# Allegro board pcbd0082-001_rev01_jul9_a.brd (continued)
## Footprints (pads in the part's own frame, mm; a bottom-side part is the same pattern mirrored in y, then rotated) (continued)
C_0402
  rect 0.508x0.533 smd: 1(0,0.419) 2(0,-0.419)
C_0402#2
  custom 0.127x0.127 smd: 1(0,0.5) 2(0,-0.5)
C_0603
  rect 0.864x0.965 smd: 1(0,0.8) 2(0,-0.8)
C_0805
  rect 1.422x1.397 smd: 1(0,1.143) 2(0,-1.143)
C_1206
  rect 1.524x1.524 smd: 1(0,1.676) 2(0,-1.676)
C_1210
  rect 1.372x2.743 smd: 1(-1.422,0) 2(1.422,0)
CON_SAM_SEAM-20-03P5-S-08-2-A-K
  round 1.778 hole 1.27 unplated: (-14.491,-3.048) (14.491,0)
  round 0.635 smd: 1(12.065,4.445) 2(12.065,3.175) 3(12.065,1.905) 4(12.065,0.635) 5(12.065,-0.635) 6(12.065,-1.905) 7(12.065,-3.175) 8(12.065,-4.445) 9(10.795,4.445) 10(10.795,3.175) 11(10.795,1.905) 12(10.795,0.635) 13(10.795,-0.635) 14(10.795,-1.905) 15(10.795,-3.175) 16(10.795,-4.445) 17(9.525,4.445) 18(9.525,3.175) 19(9.525,1.905) 20(9.525,0.635) 21(9.525,-0.635) 22(9.525,-1.905) 23(9.525,-3.175) 24(9.525,-4.445) 25(8.255,4.445) 26(8.255,3.175) 27(8.255,1.905) 28(8.255,0.635) 29(8.255,-0.635) 30(8.255,-1.905) 31(8.255,-3.175) 32(8.255,-4.445) 33(6.985,4.445) 34(6.985,3.175) 35(6.985,1.905) 36(6.985,0.635) 37(6.985,-0.635) 38(6.985,-1.905) 39(6.985,-3.175) 40(6.985,-4.445) 41(5.715,4.445) 42(5.715,3.175) 43(5.715,1.905) 44(5.715,0.635) 45(5.715,-0.635) 46(5.715,-1.905) 47(5.715,-3.175) 48(5.715,-4.445) 49(4.445,4.445) 50(4.445,3.175) 51(4.445,1.905) 52(4.445,0.635) 53(4.445,-0.635) 54(4.445,-1.905) 55(4.445,-3.175) 56(4.445,-4.445) 57(3.175,4.445) 58(3.175,3.175) 59(3.175,1.905) 60(3.175,0.635) 61(3.175,-0.635) 62(3.175,-1.905) 63(3.175,-3.175) 64(3.175,-4.445) 65(1.905,4.445) 66(1.905,3.175) 67(1.905,1.905) 68(1.905,0.635) 69(1.905,-0.635) 70(1.905,-1.905) 71(1.905,-3.175) 72(1.905,-4.445) 73(0.635,4.445) 74(0.635,3.175) 75(0.635,1.905) 76(0.635,0.635) 77(0.635,-0.635) 78(0.635,-1.905) 79(0.635,-3.175) 80(0.635,-4.445) 81(-0.635,4.445) 82(-0.635,3.175) 83(-0.635,1.905) 84(-0.635,0.635) 85(-0.635,-0.635) 86(-0.635,-1.905) 87(-0.635,-3.175) 88(-0.635,-4.445) 89(-1.905,4.445) 90(-1.905,3.175) 91(-1.905,1.905) 92(-1.905,0.635) 93(-1.905,-0.635) 94(-1.905,-1.905) 95(-1.905,-3.175) 96(-1.905,-4.445) 97(-3.175,4.445) 98(-3.175,3.175) 99(-3.175,1.905) 100(-3.175,0.635) 101(-3.175,-0.635) 102(-3.175,-1.905) 103(-3.175,-3.175) 104(-3.175,-4.445) 105(-4.445,4.445) 106(-4.445,3.175) 107(-4.445,1.905) 108(-4.445,0.635) 109(-4.445,-0.635) 110(-4.445,-1.905) 111(-4.445,-3.175) 112(-4.445,-4.445) 113(-5.715,4.445) 114(-5.715,3.175) 115(-5.715,1.905) 116(-5.715,0.635) 117(-5.715,-0.635) 118(-5.715,-1.905) 119(-5.715,-3.175) 120(-5.715,-4.445) 121(-6.985,4.445) 122(-6.985,3.175) 123(-6.985,1.905) 124(-6.985,0.635) 125(-6.985,-0.635) 126(-6.985,-1.905) 127(-6.985,-3.175) 128(-6.985,-4.445) 129(-8.255,4.445) 130(-8.255,3.175) 131(-8.255,1.905) 132(-8.255,0.635) 133(-8.255,-0.635) 134(-8.255,-1.905) 135(-8.255,-3.175) 136(-8.255,-4.445) 137(-9.525,4.445) 138(-9.525,3.175) 139(-9.525,1.905) 140(-9.525,0.635) 141(-9.525,-0.635) 142(-9.525,-1.905) 143(-9.525,-3.175) 144(-9.525,-4.445) 145(-10.795,4.445) 146(-10.795,3.175) 147(-10.795,1.905) 148(-10.795,0.635) 149(-10.795,-0.635) 150(-10.795,-1.905) 151(-10.795,-3.175) 152(-10.795,-4.445) 153(-12.065,4.445) 154(-12.065,3.175) 155(-12.065,1.905) 156(-12.065,0.635) 157(-12.065,-0.635) 158(-12.065,-1.905) 159(-12.065,-3.175) 160(-12.065,-4.445)
DHVQFN16_138_98_19P7_EP
  custom 0.07x0.07 smd: 1(-1.702,-0.25) 2(-1.25,-1.194) 3(-0.75,-1.194) 4(-0.25,-1.194) 5(0.25,-1.194) 6(0.75,-1.194) 7(1.25,-1.194) 8(1.702,-0.25) 9(1.702,0.25) 10(1.25,1.194) 11(0.75,1.194) 12(0.25,1.194) 13(-0.25,1.194) 14(-0.75,1.194) 15(-1.25,1.194) 16(-1.702,0.25)
  rect 1.981x0.965 smd: 17(0,0)
FBGA96
  round 0.356 smd: A1(-3.2,6) A2(-2.4,6) A3(-1.6,6) A7(1.6,6) A8(2.4,6) A9(3.2,6) B1(-3.2,5.2) B2(-2.4,5.2) B3(-1.6,5.2) B7(1.6,5.2) B8(2.4,5.2) B9(3.2,5.2) C1(-3.2,4.4) C2(-2.4,4.4) C3(-1.6,4.4) C7(1.6,4.4) C8(2.4,4.4) C9(3.2,4.4) D1(-3.2,3.6) D2(-2.4,3.6) D3(-1.6,3.6) D7(1.6,3.6) D8(2.4,3.6) D9(3.2,3.6) E1(-3.2,2.8) E2(-2.4,2.8) E3(-1.6,2.8) E7(1.6,2.8) E8(2.4,2.8) E9(3.2,2.8) F1(-3.2,2) F2(-2.4,2) F3(-1.6,2) F7(1.6,2) F8(2.4,2) F9(3.2,2) G1(-3.2,1.2) G2(-2.4,1.2) G3(-1.6,1.2) G7(1.6,1.2) G8(2.4,1.2) G9(3.2,1.2) H1(-3.2,0.4) H2(-2.4,0.4) H3(-1.6,0.4) H7(1.6,0.4) H8(2.4,0.4) H9(3.2,0.4) J1(-3.2,-0.4) J2(-2.4,-0.4) J3(-1.6,-0.4) J7(1.6,-0.4) J8(2.4,-0.4) J9(3.2,-0.4) K1(-3.2,-1.2) K2(-2.4,-1.2) K3(-1.6,-1.2) K7(1.6,-1.2) K8(2.4,-1.2) K9(3.2,-1.2) L1(-3.2,-2) L2(-2.4,-2) L3(-1.6,-2) L7(1.6,-2) L8(2.4,-2) L9(3.2,-2) M1(-3.2,-2.8) M2(-2.4,-2.8) M3(-1.6,-2.8) M7(1.6,-2.8) M8(2.4,-2.8) M9(3.2,-2.8) N1(-3.2,-3.6) N2(-2.4,-3.6) N3(-1.6,-3.6) N7(1.6,-3.6) N8(2.4,-3.6) N9(3.2,-3.6) P1(-3.2,-4.4) P2(-2.4,-4.4) P3(-1.6,-4.4) P7(1.6,-4.4) P8(2.4,-4.4) P9(3.2,-4.4) R1(-3.2,-5.2) R2(-2.4,-5.2) R3(-1.6,-5.2) R7(1.6,-5.2) R8(2.4,-5.2) R9(3.2,-5.2) T1(-3.2,-6) T2(-2.4,-6) T3(-1.6,-6) T7(1.6,-6) T8(2.4,-6) T9(3.2,-6)
HDR_2X15_1000_240_50_SMT_SHF
  rect 0.737x2.921 smd: 1(-8.89,-1.968) 2(-8.89,1.968) 3(-7.62,-1.968) 4(-7.62,1.968) 5(-6.35,-1.968) 6(-6.35,1.968) 7(-5.08,-1.968) 8(-5.08,1.968) 9(-3.81,-1.968) 10(-3.81,1.968) 11(-2.54,-1.968) 12(-2.54,1.968) 13(-1.27,-1.968) 14(-1.27,1.968) 15(0,-1.968) 16(0,1.968) 17(1.27,-1.968) 18(1.27,1.968) 19(2.54,-1.968) 20(2.54,1.968) 21(3.81,-1.968) 22(3.81,1.968) 23(5.08,-1.968) 24(5.08,1.968) 25(6.35,-1.968) 26(6.35,1.968) 27(7.62,-1.968) 28(7.62,1.968) 29(8.89,-1.968) 30(8.89,1.968)
IND_295_425_SMT_SLC1175
  rect 2.362x3.404 smd: 1(0,4.178) 2(0,-4.178)
IND_SMT_4X4X2P1
  rect 1.372x3.581 smd: 1(-1.219,0) 2(1.219,0)
IND_SMT_2520
  rect 1.194x2.337 smd: 1(-1.13,0) 2(1.13,0)
MG132_8_8_0P5MM
  round 1.067 smd: (-5.207,4.826) (4.826,-5.588)
  round 0.254 smd: A1(-3.25,3.25) A2(-2.75,3.25) A3(-2.25,3.25) A4(-1.75,3.25) A5(-1.25,3.25) A6(-0.75,3.25) A7(-0.25,3.25) A8(0.25,3.25) A9(0.75,3.25) A10(1.25,3.25) A11(1.75,3.25) A12(2.25,3.25) A13(2.75,3.25) A14(3.25,3.25) B1(-3.25,2.75) B2(-2.75,2.75) B5(-1.25,2.75) B9(0.75,2.75) B12(2.25,2.75) B13(2.75,2.75) B14(3.25,2.75) C1(-3.25,2.25) C3(-2.25,2.25) C4(-1.75,2.25) C5(-1.25,2.25) C6(-0.75,2.25) C7(-0.25,2.25) C8(0.25,2.25) C9(0.75,2.25) C10(1.25,2.25) C11(1.75,2.25) C12(2.25,2.25) C14(3.25,2.25) D1(-3.25,1.75) D3(-2.25,1.75) D12(2.25,1.75) D14(3.25,1.75) E1(-3.25,1.25) E3(-2.25,1.25) E12(2.25,1.25) E13(2.75,1.25) E14(3.25,1.25) F1(-3.25,0.75) F3(-2.25,0.75) F12(2.25,0.75) F14(3.25,0.75) G1(-3.25,0.25) G3(-2.25,0.25) G12(2.25,0.25) G14(3.25,0.25) H1(-3.25,-0.25) H3(-2.25,-0.25) H12(2.25,-0.25) H14(3.25,-0.25) J1(-3.25,-0.75) J3(-2.25,-0.75) J12(2.25,-0.75) J14(3.25,-0.75) K1(-3.25,-1.25) K3(-2.25,-1.25) K12(2.25,-1.25) K14(3.25,-1.25) L1(-3.25,-1.75) L3(-2.25,-1.75) L12(2.25,-1.75) L14(3.25,-1.75) M1(-3.25,-2.25) M3(-2.25,-2.25) M4(-1.75,-2.25) M5(-1.25,-2.25) M6(-0.75,-2.25) M7(-0.25,-2.25) M8(0.25,-2.25) M9(0.75,-2.25) M10(1.25,-2.25) M11(1.75,-2.25) M12(2.25,-2.25) M14(3.25,-2.25) N1(-3.25,-2.75) N2(-2.75,-2.75) N5(-1.25,-2.75) N7(-0.25,-2.75) N9(0.75,-2.75) N14(3.25,-2.75) P1(-3.25,-3.25) P2(-2.75,-3.25) P3(-2.25,-3.25) P4(-1.75,-3.25) P5(-1.25,-3.25) P6(-0.75,-3.25) P7(-0.25,-3.25) P8(0.25,-3.25) P9(0.75,-3.25) P10(1.25,-3.25) P11(1.75,-3.25) P12(2.25,-3.25) P13(2.75,-3.25) P14(3.25,-3.25)
  round 0.305 hole 0.127: B3(-2.25,2.75) B4(-1.75,2.75) B6(-0.75,2.75) B7(-0.25,2.75) B8(0.25,2.75) B10(1.25,2.75) B11(1.75,2.75) C2(-2.75,2.25) C13(2.75,2.25) D2(-2.75,1.75) D13(2.75,1.75) E2(-2.75,1.25) F2(-2.75,0.75) F13(2.75,0.75) G2(-2.75,0.25) G13(2.75,0.25) H2(-2.75,-0.25) H13(2.75,-0.25) J2(-2.75,-0.75) J13(2.75,-0.75) K2(-2.75,-1.25) K13(2.75,-1.25) L2(-2.75,-1.75) L13(2.75,-1.75) M2(-2.75,-2.25) M13(2.75,-2.25) N3(-2.25,-2.75) N4(-1.75,-2.75) N6(-0.75,-2.75) N8(0.25,-2.75) N10(1.25,-2.75) N11(1.75,-2.75) N12(2.25,-2.75) N13(2.75,-2.75)
MSOP8_193_25P6
  rect 1.524x0.406 smd: 1(-2.159,0.975) 2(-2.159,0.325) 3(-2.159,-0.325) 4(-2.159,-0.975) 5(2.159,-0.975) 6(2.159,-0.325) 7(2.159,0.325) 8(2.159,0.975)
QFN16_0300X0300X0090_0050_EP-MCRL
  rect 0.483x0.28 smd: 1(-1.36,0.75) 2(-1.36,0.25) 3(-1.36,-0.25) 4(-1.36,-0.75) 9(1.36,-0.75) 10(1.36,-0.25) 11(1.36,0.25) 12(1.36,0.75)
  rect 0.28x0.483 smd: 5(-0.75,-1.36) 6(-0.25,-1.36) 7(0.25,-1.36) 8(0.75,-1.36) 13(0.75,1.36) 14(0.25,1.36) 15(-0.25,1.36) 16(-0.75,1.36)
  rect 1.7x1.7 smd: 17(0,0)
QFN20_197_126_19P7_EP
  rect 0.66x0.279 smd: 1(-2.527,0.75) 2(-2.527,0.25) 3(-2.527,-0.25) 4(-2.527,-0.75) 11(2.527,-0.75) 12(2.527,-0.25) 13(2.527,0.25) 14(2.527,0.75)
  rect 0.279x0.66 smd: 5(-1.25,-1.626) 6(-0.75,-1.626) 7(-0.25,-1.626) 8(0.25,-1.626) 9(0.75,-1.626) 10(1.25,-1.626) 15(1.25,1.626) 16(0.75,1.626) 17(0.25,1.626) 18(-0.25,1.626) 19(-0.75,1.626) 20(-1.25,1.626)
  rect 3.785x1.981 smd: 21(0,0)
QFN36_0450X0450X0090_0040_EP-MCRL
  custom 0.051x0.051 smd: 1(-2.172,1.6) 9(-2.172,-1.6) 10(-1.6,-2.172) 18(1.6,-2.172) 19(2.172,-1.6) 27(2.172,1.6) 28(1.6,2.172) 36(-1.6,2.172)
  rect 0.711x0.203 smd: 2(-2.172,1.2) 3(-2.172,0.8) 4(-2.172,0.4) 5(-2.172,0) 6(-2.172,-0.4) 7(-2.172,-0.8) 8(-2.172,-1.2) 20(2.172,-1.2) 21(2.172,-0.8) 22(2.172,-0.4) 23(2.172,0) 24(2.172,0.4) 25(2.172,0.8) 26(2.172,1.2)
  rect 0.203x0.711 smd: 11(-1.2,-2.172) 12(-0.8,-2.172) 13(-0.4,-2.172) 14(0,-2.172) 15(0.4,-2.172) 16(0.8,-2.172) 17(1.2,-2.172) 29(1.2,2.172) 30(0.8,2.172) 31(0.4,2.172) 32(0,2.172) 33(-0.4,2.172) 34(-0.8,2.172) 35(-1.2,2.172)
  rect 1.803x1.803 smd: 37(0,0)
QFN40_236_19P7_3EP
  custom 0.07x0.07 smd: 1(-2.946,2.25) 10(-2.946,-2.25) 11(-2.25,-2.946) 20(2.25,-2.946) 21(2.946,-2.25) 30(2.946,2.25) 31(2.25,2.946) 40(-2.25,2.946)
  rect 0.813x0.279 smd: 2(-2.946,1.75) 3(-2.946,1.25) 4(-2.946,0.75) 5(-2.946,0.25) 6(-2.946,-0.25) 7(-2.946,-0.75) 8(-2.946,-1.25) 9(-2.946,-1.75) 22(2.946,-1.75) 23(2.946,-1.25) 24(2.946,-0.75) 25(2.946,-0.25) 26(2.946,0.25) 27(2.946,0.75) 28(2.946,1.25) 29(2.946,1.75)
  rect 0.279x0.813 smd: 12(-1.75,-2.946) 13(-1.25,-2.946) 14(-0.75,-2.946) 15(-0.25,-2.946) 16(0.25,-2.946) 17(0.75,-2.946) 18(1.25,-2.946) 19(1.75,-2.946) 32(1.75,2.946) 33(1.25,2.946) 34(0.75,2.946) 35(0.25,2.946) 36(-0.25,2.946) 37(-0.75,2.946) 38(-1.25,2.946) 39(-1.75,2.946)
  rect 1.499x2.007 smd: 41(-1.448,1.194) 42(-1.448,-1.194)
  rect 2.388x4.394 smd: 43(1.003,0)
QFN40_236_19P7_EP165
  custom 0.07x0.07 smd: 1(-2.946,2.25) 10(-2.946,-2.25) 11(-2.25,-2.946) 20(2.25,-2.946) 21(2.946,-2.25) 30(2.946,2.25) 31(2.25,2.946) 40(-2.25,2.946)
  rect 0.813x0.279 smd: 2(-2.946,1.75) 3(-2.946,1.25) 4(-2.946,0.75) 5(-2.946,0.25) 6(-2.946,-0.25) 7(-2.946,-0.75) 8(-2.946,-1.25) 9(-2.946,-1.75) 22(2.946,-1.75) 23(2.946,-1.25) 24(2.946,-0.75) 25(2.946,-0.25) 26(2.946,0.25) 27(2.946,0.75) 28(2.946,1.25) 29(2.946,1.75)
  rect 0.279x0.813 smd: 12(-1.75,-2.946) 13(-1.25,-2.946) 14(-0.75,-2.946) 15(-0.25,-2.946) 16(0.25,-2.946) 17(0.75,-2.946) 18(1.25,-2.946) 19(1.75,-2.946) 32(1.75,2.946) 33(1.25,2.946) 34(0.75,2.946) 35(0.25,2.946) 36(-0.25,2.946) 37(-0.75,2.946) 38(-1.25,2.946) 39(-1.75,2.946)
  rect 4.191x4.191 smd: 41(0,0)
R_0402
  rect 0.508x0.533 smd: 1(0,0.419) 2(0,-0.419)
R_0402#2
  custom 0.127x0.127 smd: 1(0,0.5) 2(0,-0.5)
R_0603
  rect 0.762x0.965 smd: 1(0,0.8) 2(0,-0.8)
S-WQFN-N20
  custom 0.051x0.051 smd: 1(-1.499,0.8) 2(-1.499,0.4) 3(-1.499,0) 4(-1.499,-0.4) 5(-1.499,-0.8) 6(-0.8,-1.499) 7(-0.4,-1.499) 8(0,-1.499) 9(0.4,-1.499) 10(0.8,-1.499) 11(1.499,-0.8) 12(1.499,-0.4) 13(1.499,0) 14(1.499,0.4) 15(1.499,0.8) 16(0.8,1.499) 17(0.4,1.499) 18(0,1.499) 19(-0.4,1.499) 20(-0.8,1.499)
  rect 1.575x1.575 smd: 21(0,0)
SMC_ECE-CAP_10P2MM
  rect 1.905x4.42 smd: 1(0,4.356) 2(0,-4.356)
SO8_244_50
  rect 2.032x0.635 smd: 1(-2.667,1.905) 2(-2.667,0.635) 3(-2.667,-0.635) 4(-2.667,-1.905) 5(2.667,-1.905) 6(2.667,-0.635) 7(2.667,0.635) 8(2.667,1.905)
SO8W_208MILS
  rect 1.829x0.635 smd: 1(-3.645,1.905) 2(-3.645,0.635) 3(-3.645,-0.635) 4(-3.645,-1.905) 5(3.645,-1.905) 6(3.645,-0.635) 7(3.645,0.635) 8(3.645,1.905)
SOD80
  rect 1.016x1.702 smd: 1(1.651,0) 2(-1.651,0)
SON8_130_25P6_EP_Q3D
  custom 0.203x0.203 smd: 1(-1.6,0.975)
  round 0 smd: 2(-1.524,0.381)
  rect 0.813x0.406 smd: 3(-1.6,-0.325) 4(-1.6,-0.975) 5(1.6,-0.975) 6(1.6,-0.325) 7(1.6,0.325) 8(1.6,0.975)
  rect 1.778x2.743 smd: 9(0,0)
TP50SQ_SMT
  rect 1.27x1.27 smd: 1(0,0)
unnamed#2
  round 1.067 smd: (0,0)
unnamed#3
  round 4.508 hole 4 unplated: (-54.991,-18.009) (-17.45,-54)
unnamed#4
  round 0.254 hole 0.762 unplated: (0,0) (0,1.27) (0,2.54) (0,3.81)
VPIN
  round 0.762 hole 0.206: 1(0,0)

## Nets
0.7V_REF: D5.1(N1) R278.1(N1) U4.2(IN1-) U4.6(IN2-)
GND: C1.2(N2) C2.2(N2) C3.2(N2) C4.2(N2) C5.2(N2) C7.2(N2) C8.2(N2) C9.2(N2) C10.2(N2) C11.2(N2) C12.2(N2) C13.2(N2) C14.2(N2) C15.2(N2) C16.2(N2) C17.2(N2) C18.2(N2) C19.2(N2) C20.2(N2) C21.2(N2) C22.2(N2) C23.2(N2) C24.2(N2) C25.2(N2) C26.2(N2) C27.2(N2) C28.2(N2) C29.2(N2) C30.2(N2) C31.2(N2) C36.2(N2) C37.2(N2) C38.2(N2) C39.2(N2) C40.2(N2) C41.2(N2) C42.2(N2) C43.2(N2) C44.2(N2) C46.2(N2) C47.2(N2) C50.2(N2) C51.2(N2) C57.2(N2) C58.2(N2) C59.2(N2) C60.2(N2) C61.2(N2) C62.2(N2) C63.2(N2) C64.2(N2) C65.2(N2) C66.2(N2) C67.2(N2) C68.2(N2) C74.2(N2) C76.2(N2) C77.2(N2) C78.2(N2) C79.2(N2) C80.2(N2) C81.2(N2) C82.2(N2) C83.2(N2) C84.2(N2) C85.2(N2) C86.2(N2) C87.2(N2) C89.2(N2) C90.2(N2) C91.2(N2) C92.2(N2) C93.2(N2) C94.2(N2) C101.2(N2) C102.2(N2) C103.2(N2) C109.2(N2) C110.2(N2) C116.2(N2) C118.2(N2) C119.2(N2) C120.2(N2) C121.2(N2) C122.2(N2) C123.2(N2) C124.2(N2) C126.2(N2) C128.2(N2) C130.2(N2) C131.2(N2) C132.2(N2) C133.2(N2) C134.2(N2) C135.2(N2) C136.2(N2) C137.2(N2) C138.2(N2) C139.2(N2) C140.2(N2) C141.2(N2) C142.2(N2) C143.2(N2) C144.2(N2) C161.2(N2) C162.2(N2) C163.2(N2) C165.2(N2) C166.2(N2) C167.2(N2) C168.2(N2) C169.2(N2) C170.2(N2) C171.2(N2) C172.2(N2) C173.2(N2) C174.2(N2) C175.2(N2) C176.2(N2) C177.2(N2) C178.2(N2) C179.2(N2) C180.2(N2) C181.2(N2) C182.2(N2) C183.2(N2) C184.2(N2) C186.2(N2) C187.2(N2) C190.2(N2) C191.2(N2) C192.2(N2) C193.2(N2) C194.2(N2) C195.2(N2) C196.2(N2) C197.2(N2) C198.2(N2) C199.2(N2) C200.2(N2) C201.2(N2) C202.2(N2) C203.2(N2) C204.2(N2) C205.2(N2) C206.2(N2) C211.2(N2) C212.2(N2) C213.2(N2) C214.2(N2) C215.2(N2) C216.2(N2) C217.2(N2) C218.2(N2) C219.2(N2) C220.2(N2) C242.2(NEG) C243.2(NEG) C248.2(N2) C249.2(N2) C263.2(N2) C264.2(N2) C265.2(N2) C266.2(N2) C268.2(N2) C269.2(N2) C270.2(N2) C271.2(N2) C272.2(N2) C273.2(N2) C274.2(N2) C275.2(N2) C276.2(N2) C277.2(N2) C278.2(N2) C279.2(N2) C280.2(N2) C281.2(N2) C282.2(N2) C283.2(N2) C284.2(N2) C285.2(N2) D5.2(N2) J4.1(ROW1) J4.3(ROW1) J4.7(ROW1) J4.10(ROW2) J4.12(ROW2) J4.15(ROW2) J4.18(ROW3) J4.20(ROW3) J4.22(ROW3) J4.23(ROW3) J4.24(ROW3) J4.25(ROW4) J4.27(ROW4) J4.29(ROW4) J4.31(ROW4) J4.33(ROW5) J4.35(ROW5) J4.37(ROW5) J4.39(ROW5) J4.42(ROW6) J4.44(ROW6) J4.46(ROW6) J4.48(ROW6) J4.50(ROW7) J4.52(ROW7) J4.54(ROW7) J4.56(ROW7) J4.57(ROW8) J4.59(ROW8) J4.61(ROW8) J4.63(ROW8) J4.65(ROW9) J4.67(ROW9) J4.69(ROW9) J4.71(ROW9) J4.74(ROW10) J4.76(ROW10) J4.78(ROW10) J4.80(ROW10) J4.82(ROW11) J4.84(ROW11) J4.86(ROW11) J4.88(ROW11) J4.89(ROW12) J4.91(ROW12) J4.93(ROW12) J4.95(ROW12) J4.97(ROW13) J4.99(ROW13) J4.101(ROW13) J4.103(ROW13) J4.106(ROW14) J4.108(ROW14) J4.110(ROW14) J4.112(ROW14) J4.114(ROW15) J4.116(ROW15) J4.118(ROW15) J4.120(ROW15) J4.121(ROW16) J4.123(ROW16) J4.125(ROW16) J4.127(ROW16) J4.131(ROW17) J4.133(ROW17) J4.135(ROW17) J4.138(ROW18) J4.140(ROW18) J4.142(ROW18) J4.144(ROW18) J4.148(ROW19) J4.150(ROW19) J4.157(ROW20) J4.159(ROW20) J5.4 J5.12 J5.27 Q1.9(PGND) R1.1(N1) R4.1(N1) R16.2(N2) R18.2(N2) R32.2(N2) R45.2(N2) R46.2(N2) R47.2(N2) R49.2(N2) R54.2(N2) R55.2(N2) R56.2(N2) R57.2(N2) R58.2(N2) R59.2(N2) R60.2(N2) R64.2(N2) R65.2(N2) R72.2(N2) R80.1(N1) R81.1(N1) R82.1(N1) R83.1(N1) R88.1(N1) R91.1(N1) R95.1(N1) R96.1(N1) R97.1(N1) R101.1(N1) R102.1(N1) R103.1(N1) R105.1(N1) R107.1(N1) R113.1(N1) R124.1(N1) R146.1(N1) R149.1(N1) R152.2(N2) R186.1(N1) R187.1(N1) R188.1(N1) R189.1(N1) R283.1(N1) R285.1(N1) R289.1(N1) R308.1(N1) R316.1(N1) R317.1(N1) R318.1(N1) R319.1(N1) R320.1(N1) R321.1(N1) R322.1(N1) R339.1(N1) R352.1(N1) R353.1(N1) R361.1(N1) R363.1(N1) R371.2(N2) R372.2(N2) R375.2(N2) R376.2(N2) R400.1(N1) R407.2(N2) R408.2(N2) R411.1(N1) TP39.1 TP40.1 TP41.1 TP43.1 TP45.1 TP47.1 TP49.1 TP51.1 TP53.1 TP55.1 TP69.1 U1.A2(VSS_5) U1.A3(VSS_10) U1.A4(VSS_13) U1.A5(VSS_14) U1.A6(VSS_15) U1.A7(VSS_16) U1.A8(VSS_17) U1.A9(VSS_18) U1.A10(VSS) U1.A12(VSS_1) U1.A14(VSS_2) U1.A16(VSS_3) U1.A18(VSS_4) U1.A20(VSS_6) U1.A22(VSS_7) U1.A24(VSS_8) U1.A26(VSS_9) U1.A30(VSS_11) U1.A31(VSS_12) U1.AA12(VSS_19) U1.AA14(VSS_20) U1.AA16(VSS_21) U1.AA18(VSS_22) U1.AA20(VSS_23) U1.AA22(VSS_24) U1.AA24(VSS_25) U1.AA26(VSS_26) U1.AB2(VSS_32) U1.AB5(VSS_36) U1.AB8(VSS_37) U1.AB11(VSS_27) U1.AB13(VSS_28) U1.AB15(VSS_29) U1.AB17(VSS_30) U1.AB19(VSS_31) U1.AB21(VSS_33) U1.AB23(VSS_34) U1.AB25(VSS_35) U1.AC12(VSS_38) U1.AC14(VSS_39) U1.AC16(VSS_40) U1.AC20(VSS_41) U1.AC22(VSS_42) U1.AC26(VSS_43) U1.AC29(VSS_44) U1.AD10(VSS_45) U1.AD11(VSS_46) U1.AD13(VSS_47) U1.AD15(VSS_48) U1.AD17(VSS_49) U1.AD19(VSS_50) U1.AD21(VSS_51) U1.AD23(VSS_52) U1.AD25(VSS_53) U1.AD31(VSS_54) U1.AE10(PCIE1_SYSCLK_INP) U1.AE11(PCIE1_SYSCLK_INN) U1.AE12(VSS_55) U1.AE16(VSS_56) U1.AE18(VSS_57) U1.AE20(VSS_58) U1.AE27(VSS_59) U1.AF3(VSS_66) U1.AF4(VSS_67) U1.AF6(VSS_68) U1.AF8(VSS_69) U1.AF9(VDDA_PCIE1_2) U1.AF10(VDDA_PCIE1) U1.AF11(VDDA_PCIE1_1) U1.AF18(VSS_61) U1.AF24(VSS_64) U1.AF26(VSS_65) U1.AG3(VSS_80) U1.AG4(PCIE1_RXN0) U1.AG5(VSS_81) U1.AG6(PCIE1_RXN2) U1.AG7(VSS_82) U1.AG8(PCIE1_RXN4) U1.AG9(VSS_83) U1.AG10(PCIE1_RXN6) U1.AG11(VSS_70) U1.AG13(VSS_71) U1.AG15(VSS_72) U1.AG17(VSS_73) U1.AG19(VSS_74) U1.AG21(VSS_75) U1.AG22(SERDES0_RXN2) U1.AG23(VSS_76) U1.AG25(VSS_77) U1.AG27(VSS_78) U1.AG28(SERDES2_RXN0) U1.AG29(VSS_79) U1.AH3(VSS_84) U1.AH4(PCIE1_RXP0) U1.AH5(PCIE1_RXN1) U1.AH6(PCIE1_RXP2) U1.AH7(PCIE1_RXN3) U1.AH8(PCIE1_RXP4) U1.AH9(PCIE1_RXN5) U1.AH10(PCIE1_RXP6) U1.AH11(PCIE1_RXN7) U1.AH21(SERDES0_RXN1) U1.AH22(SERDES0_RXP2) U1.AH23(SERDES0_RXN3) U1.AH28(SERDES2_RXP0) U1.AH29(SERDES2_RXN1) U1.AH30(VSS_85) U1.AJ1(VSS_86) U1.AJ2(VSS_92) U1.AJ3(VDDAH_PCIE0) U1.AJ4(VSS_99) U1.AJ5(PCIE1_RXP1) U1.AJ6(VSS_100) U1.AJ7(PCIE1_RXP3) U1.AJ8(VSS_101) U1.AJ9(PCIE1_RXP5) U1.AJ10(VSS_87) U1.AJ11(PCIE1_RXP7) U1.AJ12(VSS_88) U1.AJ14(VSS_89) U1.AJ16(VSS_90) U1.AJ18(VSS_91) U1.AJ20(VSS_93) U1.AJ21(SERDES0_RXP1) U1.AJ22(VSS_94) U1.AJ23(SERDES0_RXP3) U1.AJ24(VSS_95) U1.AJ26(VSS_96) U1.AJ28(VSS_97) U1.AJ29(SERDES2_RXP1) U1.AJ30(VSS_98) U1.AK1(VSS_102) U1.AK2(VSS_108) U1.AK3(VDDAH_PCIE1) U1.AK5(VSS_115) U1.AK7(VSS_116) U1.AK9(VSS_117) U1.AK11(VSS_103) U1.AK13(VSS_104) U1.AK15(VSS_105) U1.AK17(VSS_106) U1.AK19(VSS_107) U1.AK21(VSS_109) U1.AK23(VSS_110) U1.AK25(VSS_111) U1.AK27(VSS_112) U1.AK29(VSS_113) U1.AK30(VDDAH_SERDES012) U1.AK32(VSS_114) U1.AL1(VSS_118) U1.AL2(VSS_119) U1.AL3(VSS_120) U1.AL30(VDDAH_SERDES012_1) U1.AL31(VSS_121) U1.AL32(VSS_122) U1.AM2(VSS_128) U1.AM3(VSS_134) U1.AM4(VSS_137) U1.AM6(VSS_138) U1.AM8(VSS_139) U1.AM10(VSS_123) U1.AM12(VSS_124) U1.AM14(VSS_125) U1.AM16(VSS_126) U1.AM18(VSS_127) U1.AM20(VSS_129) U1.AM22(VSS_130) U1.AM24(VSS_131) U1.AM26(VSS_132) U1.AM28(VSS_133) U1.AM30(VSS_135) U1.AM31(VSS_136) U1.B1(VSS_140) U1.B3(VSS_150) U1.B5(VSS_153) U1.B7(VSS_154) U1.B9(VSS_155) U1.B10(VSS_141) U1.B11(VSS_142) U1.B13(VSS_143) U1.B15(VSS_144) U1.B17(VSS_145) U1.B19(VSS_146) U1.B21(VSS_147) U1.B23(VSS_148) U1.B25(VSS_149) U1.B31(VSS_151) U1.B32(VSS_152) U1.C1(VSS_156) U1.C10(VSS_157) U1.C12(VSS_158) U1.C14(VSS_159) U1.C16(VSS_160) U1.C18(VSS_161) U1.C20(VSS_162) U1.C22(VSS_163) U1.C24(VSS_164) U1.C26(VSS_165) U1.C32(VSS_166) U1.D10(VSS_167) U1.D11(VSS_168) U1.D13(VSS_169) U1.D15(VSS_170) U1.D17(VSS_171) U1.D19(VSS_172) U1.D21(VSS_173) U1.D23(VSS_174) U1.D25(VSS_175) U1.D28(VSS_176) U1.E10(VSS_177) U1.E12(VSS_178) U1.E14(VSS_179) U1.E16(VSS_180) U1.E18(VSS_181) U1.E20(VSS_182) U1.E22(VSS_183) U1.E24(VSS_184) U1.E26(VSS_185) U1.F4(VSS_197) U1.F8(VSS_198) U1.F10(VSS_186) U1.F11(VSS_187) U1.F13(VSS_188) U1.F15(VSS_189) U1.F17(VSS_190) U1.F19(VSS_191) U1.F21(VSS_192) U1.F23(VSS_193) U1.F25(VSS_194) U1.F27(VSS_195) U1.F31(VSS_196) U1.G10(VSS_199) U1.G12(VSS_200) U1.G14(VSS_201) U1.G16(VSS_202) U1.G18(VSS_203) U1.G20(VSS_204) U1.G22(VSS_205) U1.G24(VSS_206) U1.G26(VSS_207) U1.H11(VSS_208) U1.H13(VSS_209) U1.H15(VSS_210) U1.H17(VSS_211) U1.H19(VSS_212) U1.H21(VSS_213) U1.H23(VSS_214) U1.H25(VSS_215) U1.H27(VSS_216) U1.J12(VSS_217) U1.J14(VSS_218) U1.J16(VSS_219) U1.J18(VSS_220) U1.J20(VSS_221) U1.J22(VSS_222) U1.J24(VSS_223) U1.J26(VSS_224) U1.K3(VSS_233) U1.K6(VSS_235) U1.K11(VSS_225) U1.K13(VSS_226) U1.K15(VSS_227) U1.K17(VSS_228) U1.K19(VSS_229) U1.K21(VSS_230) U1.K23(VSS_231) U1.K25(VSS_232) U1.K31(VSS_234) U1.L12(VSS_236) U1.L14(VSS_237) U1.L16(VSS_238) U1.L18(VSS_239) U1.L20(VSS_240) U1.L22(VSS_241) U1.L24(VSS_242) U1.L26(VSS_243) U1.L27(VSS_244) U1.M11(VSS_245) U1.M13(VSS_246) U1.M15(VSS_247) U1.M17(VSS_248) U1.M19(VSS_249) U1.M21(VSS_250) U1.M23(VSS_251) U1.M25(VSS_252) U1.N12(VSS_253) U1.N14(VSS_254) U1.N16(VSS_255) U1.N18(VSS_256) U1.N20(VSS_257) U1.N22(VSS_258) U1.N24(VSS_259) U1.N26(VSS_260) U1.N29(VSS_261) U1.P2(VSS_267) U1.P5(VSS_272) U1.P8(VSS_273) U1.P11(VSS_262) U1.P13(VSS_263) U1.P15(VSS_264) U1.P17(VSS_265) U1.P19(VSS_266) U1.P21(VSS_268) U1.P23(VSS_269) U1.P25(VSS_270) U1.P27(VSS_271) U1.P31(PCIE1_RESET_IN_L) U1.R12(VSS_274) U1.R14(VSS_275) U1.R16(VSS_276) U1.R18(VSS_277) U1.R20(VSS_278) U1.R22(VSS_279) U1.R24(VSS_280) U1.R26(VSS_281) U1.R31(VSS_282) U1.T11(VSS_283) U1.T13(VSS_284) U1.T15(VSS_285) U1.T17(VSS_286) U1.T19(VSS_287) U1.T21(VSS_288) U1.T23(VSS_289) U1.T25(VSS_290) U1.T28(VSS_291) U1.U12(VSS_292) U1.U14(VSS_293) U1.U16(VSS_294) U1.U18(VSS_295) U1.U20(VSS_296) U1.U22(VSS_297) U1.U24(VSS_298) U1.V3(VSS_308) U1.V6(VSS_309) U1.V11(VSS_299) U1.V13(VSS_300) U1.V15(VSS_301) U1.V17(VSS_302) U1.V19(VSS_303) U1.V21(VSS_304) U1.V23(VSS_305) U1.V25(VSS_306) U1.V26(VSS_307) U1.V28(TEST_JTAG_BYPASS) U1.V29(TEST_SCAN_MODE) U1.W12(VSS_310) U1.W14(VSS_311) U1.W16(VSS_312) U1.W18(VSS_313) U1.W20(VSS_314) U1.W22(VSS_315) U1.W24(VSS_316) U1.W27(TEST_SHIFT_EN) U1.W30(VSS_317) U1.Y11(VSS_318) U1.Y13(VSS_319) U1.Y15(VSS_320) U1.Y17(VSS_321) U1.Y19(VSS_322) U1.Y21(VSS_323) U1.Y25(VSS_324) U1.Y27(TEST_SCAN_CLK) U2.A5(GND8) U2.B11(GND7) U2.D2(GND1) U2.D13(GND6) U2.G2(GND9) U2.H13(GND10) U2.L2(GND2) U2.L13(GND5) U2.P5(GND3) U2.P10(GND4) U3.4(VTTGND) U3.7(GND) U3.10(PGND) U3.21(GND_EP) U4.4(V-) U5.5(CGND1) U5.16(PGND1) U5.17(PGND2) U5.18(PGND3) U5.19(PGND4) U5.20(PGND5) U5.21(PGND6) U5.22(PGND7) U5.23(PGND8) U5.24(PGND9) U5.25(PGND10) U5.26(PGND11) U5.27(PGND12) U5.28(PGND13) U5.37(CGND2) U5.41(CGND3) U6.5(CGND1) U6.16(PGND1) U6.17(PGND2) U6.18(PGND3) U6.19(PGND4) U6.20(PGND5) U6.21(PGND6) U6.22(PGND7) U6.23(PGND8) U6.24(PGND9) U6.25(PGND10) U6.26(PGND11) U6.27(PGND12) U6.28(PGND13) U6.37(CGND2) U6.41(CGND3) U7.4(VSS) U8.4(VSS) U9.6(PGND3) U9.10(PGND4) U9.14(AGND1) U9.18(PGND5) U9.22(PGND6) U9.23(SW6) U9.28(PGND1) U9.32(AGND2) U9.36(PGND2) U9.37(EPAD) U10.7(GND) U10.41(EPAD) U12.8(VSS) U12.17(PAD_VSS) U13.4(AGND) U13.14(PGND_1) U13.15(PGND_2) U13.17(EPAD) U14.3(VSS1) U14.4(VSS2) U14.13(VSS3) U14.14(VSS4) U14.21(EPAD) U15.4(VSS) U17.A9(VSS3) U17.B1(VSSQ4) U17.B3(VSS7) U17.B9(VSSQ7) U17.D1(VSSQ3) U17.D8(VSSQ0) U17.E1(VSS11) U17.E2(VSSQ1) U17.E8(VSSQ8) U17.F9(VSSQ6) U17.G1(VSSQ2) U17.G8(VSS5) U17.G9(VSSQ5) U17.J2(VSS6) U17.J8(VSS4) U17.M1(VSS10) U17.M9(VSS2) U17.P1(VSS9) U17.P9(VSS1) U17.T1(VSS8) U17.T9(VSS0) U18.A9(VSS3) U18.B1(VSSQ4) U18.B3(VSS7) U18.B9(VSSQ7) U18.D1(VSSQ3) U18.D8(VSSQ0) U18.E1(VSS11) U18.E2(VSSQ1) U18.E8(VSSQ8) U18.F9(VSSQ6) U18.G1(VSSQ2) U18.G8(VSS5) U18.G9(VSSQ5) U18.J2(VSS6) U18.J8(VSS4) U18.M1(VSS10) U18.M9(VSS2) U18.P1(VSS9) U18.P9(VSS1) U18.T1(VSS8) U18.T9(VSS0) U19.A9(VSS3) U19.B1(VSSQ4) U19.B3(VSS7) U19.B9(VSSQ7) U19.D1(VSSQ3) U19.D8(VSSQ0) U19.E1(VSS11) U19.E2(VSSQ1) U19.E8(VSSQ8) U19.F9(VSSQ6) U19.G1(VSSQ2) U19.G8(VSS5) U19.G9(VSSQ5) U19.J2(VSS6) U19.J8(VSS4) U19.M1(VSS10) U19.M9(VSS2) U19.P1(VSS9) U19.P9(VSS1) U19.T1(VSS8) U19.T9(VSS0) U20.8(VSS) U20.17(PAD_VSS) U21.8(VSS) U21.17(PAD_VSS)
VDD_1.2V: C20.1(N1) C270.1(N1) C274.1(N1) L10.1(N1) R77.2(N2) R78.2(N2) R79.2(N2) R84.2(N2) R90.2(N2) R92.2(N2) R93.2(N2) R94.2(N2) TP48.1 U1.AF28(VDD_VID) U1.AF29(VDD_VID_1) U9.29(OUT1)
VDD_1.5V: C22.1(N1) L11.1(N1) L13.1(N1) L14.2(N2) TP46.1 U9.3(OUT2)
VDD_1.8V: C19.1(N1) C269.1(N1) C273.1(N1) L1.1(N1) L15.1(N1) L19.1(N1) TP50.1 U1.U26(VDD18_LVTTL) U1.U27(VDD18_LVTTL_1) U9.7(OUT3)
VDD_3.3V: C23.1(N1) C85.1(N1) C87.1(N1) C268.1(N1) C271.1(N1) C272.1(N1) C275.1(N1) C276.1(N1) C277.1(N1) L20.2(N2) R19.1(N1) R20.1(N1) R21.1(N1) R22.1(N1) R23.1(N1) R24.1(N1) R25.1(N1) R26.1(N1) R27.1(N1) R28.1(N1) R29.1(N1) R30.1(N1) R31.1(N1) R34.2(N2) R41.1(N1) R42.1(N1) R43.1(N1) R44.1(N1) R66.1(N1) R67.1(N1) R68.1(N1) R75.2(N2) R76.2(N2) R89.2(N2) R365.2(N2) R393.2(N2) R394.2(N2) R403.1(N1) R404.1(N1) R405.1(N1) R406.1(N1) TP56.1 U1.AA27(VDD33_LVTTL) U1.AB26(VDD33_LVTTL_1) U1.AD27(VDD33_LVTTL_2) U1.V27(VDD33_LVTTL_3) U1.W26(VDD33_LVTTL_4) U1.Y26(VDD33_LVTTL_5) U7.8(VCC) U8.8(VCC) U9.17(OUT5) U15.8(VCC)
VDD_5.0V: C131.1(N1) C132.1(N1) C133.1(N1) C134.1(N1) C135.1(N1) C141.1(N1) C181.1(N1) C182.1(N1) C201.1(N1) C202.1(N1) C203.1(N1) C204.1(N1) L21.2(N2) R74.1(N1) R98.2(N2) R104.2(N2) R112.2(N2) R126.1(N1) R180.2(N2) R181.2(N2) R331.1(N1) R411.2(N2) TP42.1 U5.2(VCIN) U6.2(VCIN) U9.2(PVIN2) U9.4(PVIN3) U9.8(PVIN4) U9.20(PVIN5) U9.21(OUT6) U9.24(PVIN6O) U9.25(PVIN6) U9.26(PVIN1) U9.31(AVIN)
VDD_5.0V_EN: R400.2(N2) TP67.1 U2.J13(PR6A) U13.9(EN)
VDD_5.0V_PGOOD: R99.1(N1) TP61.1 U2.C2(PL2C/PCLKT3_2) U13.8(PG)
VDD_7401_EN: R103.2(N2) TP66.1 U2.G14(PR5B) U9.30(EN)
VDD_7401_PGOOD: R100.1(N1) TP64.1 U2.D1(PL2D/PCLKC3_2) U9.35(PG)
VDD_CORE: C3.1(N1) C4.1(N1) C5.1(N1) C7.1(N1) C8.1(N1) C9.1(N1) C10.1(N1) C11.1(N1) C12.1(N1) C13.1(N1) C14.1(N1) C15.1(N1) C16.1(N1) C17.1(N1) C18.1(N1) C58.1(N1) C59.1(N1) C60.1(N1) C61.1(N1) C62.1(N1) C63.1(N1) C64.1(N1) C65.1(N1) C77.1(N1) C78.1(N1) C79.1(N1) C80.1(N1) C161.1(N1) C162.1(N1) C163.1(N1) C166.1(N1) C167.1(N1) C168.1(N1) C173.1(N1) C174.1(N1) C175.1(N1) C176.1(N1) C177.1(N1) C178.1(N1) C197.1(N1) C198.1(N1) C199.1(N1) C200.1(N1) L2.1(N1) L3.1(N1) L17.2(N2) L18.2(N2) R144.1(N1) R145.1(N1) R166.1(N1) R167.1(N1) R286.2(N2) TP37.1 U1.A11(VDD_CORE1) U1.A13(VDD_CORE1_1) U1.A15(VDD_CORE1_2) U1.A17(VDD_CORE1_3) U1.A19(VDD_CORE1_4) U1.A21(VDD_CORE1_5) U1.A23(VDD_CORE1_6) U1.A25(VDD_CORE1_7) U1.AA11(VDD_CORE1_8) U1.AA13(VDD_CORE1_9) U1.AA15(VDD_CORE1_10) U1.AA17(VDD_CORE1_11) U1.AA19(VDD_CORE1_12) U1.AA21(VDD_CORE1_13) U1.AA23(VDD_CORE1_14) U1.AA25(VDD_CORE1_15) U1.AB12(VDD_CORE1_16) U1.AB14(VDD_CORE1_17) U1.AB16(VDD_CORE1_18) U1.AB18(VDD_CORE1_19) U1.AB20(VDD_CORE1_20) U1.AB22(VDD_CORE1_21) U1.AB24(VDD_CORE1_22) U1.AC11(VDD_CORE1_23) U1.AC13(VDD_CORE1_24) U1.AC15(VDD_CORE1_25) U1.AC17(VDD_CORE1_26) U1.AC19(VDD_CORE1_27) U1.AC21(VDD_CORE1_28) U1.AC23(VDD_CORE1_29) U1.AD12(VDD_CORE1_30) U1.AD14(VDD_CORE1_31) U1.AD16(VDD_CORE1_32) U1.AD18(VDD_CORE1_33) U1.AD20(VDD_CORE1_34) U1.AD22(VDD_CORE1_35) U1.AD24(VDD_CORE1_36) U1.AD26(VDD_CORE1_37) U1.AE15(VDD_CORE1_38) U1.AE17(VDD_CORE1_39) U1.AE19(VDD_CORE1_40) U1.AE21(VDD_CORE1_41) U1.B12(VDD_CORE1_42) U1.B14(VDD_CORE1_43) U1.B16(VDD_CORE1_44) U1.B18(VDD_CORE1_45) U1.B20(VDD_CORE1_46) U1.B22(VDD_CORE1_47) U1.B24(VDD_CORE1_48) U1.B26(VDD_CORE1_49) U1.C11(VDD_CORE1_50) U1.C13(VDD_CORE1_51) U1.C15(VDD_CORE1_52) U1.C17(VDD_CORE1_53) U1.C19(VDD_CORE1_54) U1.C21(VDD_CORE1_55) U1.C23(VDD_CORE1_56) U1.C25(VDD_CORE1_57) U1.D12(VDD_CORE1_58) U1.D14(VDD_CORE1_59) U1.D16(VDD_CORE1_60) U1.D18(VDD_CORE1_61) U1.D20(VDD_CORE1_62) U1.D22(VDD_CORE1_63) U1.D24(VDD_CORE1_64) U1.D26(VDD_CORE1_65) U1.E11(VDD_CORE1_66) U1.E13(VDD_CORE1_67) U1.E15(VDD_CORE1_68) U1.E17(VDD_CORE1_69) U1.E19(VDD_CORE1_70) U1.E21(VDD_CORE1_71) U1.E23(VDD_CORE1_72) U1.E25(VDD_CORE1_73) U1.E27(VDD_CORE1_74) U1.F12(VDD_CORE1_75) U1.F14(VDD_CORE1_76) U1.F16(VDD_CORE1_77) U1.F18(VDD_CORE1_78) U1.F20(VDD_CORE1_79) U1.F22(VDD_CORE1_80) U1.F24(VDD_CORE1_81) U1.F26(VDD_CORE1_82) U1.G11(VDD_CORE1_83) U1.G13(VDD_CORE1_84) U1.G15(VDD_CORE1_85) U1.G17(VDD_CORE1_86) U1.G19(VDD_CORE1_87) U1.G21(VDD_CORE1_88) U1.G23(VDD_CORE1_89) U1.G25(VDD_CORE1_90) U1.G27(VDD_CORE1_91) U1.H12(VDD_CORE1_92) U1.H14(VDD_CORE1_93) U1.H16(VDD_CORE1_94) U1.H18(VDD_CORE1_95) U1.H20(VDD_CORE1_96) U1.H22(VDD_CORE1_97) U1.H24(VDD_CORE1_98) U1.H26(VDD_CORE1_99) U1.J11(VDD_CORE1_100) U1.J13(VDD_CORE1_101) U1.J15(VDD_CORE1_102) U1.J17(VDD_CORE1_103) U1.J19(VDD_CORE1_104) U1.J21(VDD_CORE1_105) U1.J23(VDD_CORE1_106) U1.J25(VDD_CORE1_107) U1.K12(VDD_CORE1_108) U1.K14(VDD_CORE1_109) U1.K16(VDD_CORE1_110) U1.K18(VDD_CORE1_111) U1.K20(VDD_CORE1_112) U1.K22(VDD_CORE1_113) U1.K24(VDD_CORE1_114) U1.K26(VDD_CORE1_115) U1.L11(VDD_CORE1_116) U1.L13(VDD_CORE1_117) U1.L15(VDD_CORE1_118) U1.L17(VDD_CORE1_119) U1.L19(VDD_CORE1_120) U1.L21(VDD_CORE1_121) U1.L23(VDD_CORE1_122) U1.L25(VDD_CORE1_123) U1.L29(VDD_FUSE1) U1.L30(VDD_FUSE3) U1.L31(VDD_FUSE4) U1.M12(VDD_CORE1_124) U1.M14(VDD_CORE1_125) U1.M16(VDD_CORE1_126) U1.M18(VDD_CORE1_127) U1.M20(VDD_CORE1_128) U1.M22(VDD_CORE1_129) U1.M24(VDD_CORE1_130) U1.M26(VDD_CORE1_131) U1.M30(VDD_FUSE2) U1.N11(VDD_CORE1_132) U1.N13(VDD_CORE1_133) U1.N15(VDD_CORE1_134) U1.N17(VDD_CORE1_135) U1.N19(VDD_CORE1_136) U1.N21(VDD_CORE1_137) U1.N23(VDD_CORE1_138) U1.N25(VDD_CORE1_139) U1.P12(VDD_CORE1_140) U1.P14(VDD_CORE1_141) U1.P16(VDD_CORE1_142) U1.P18(VDD_CORE1_143) U1.P20(VDD_CORE1_144) U1.P22(VDD_CORE3) U1.P24(VDD_CORE3_1) U1.P26(VDD_CORE1_145) U1.R11(VDD_CORE1_146) U1.R13(VDD_CORE1_147) U1.R15(VDD_CORE1_148) U1.R17(VDD_CORE1_149) U1.R19(VDD_CORE1_150) U1.R21(VDD_CORE1_151) U1.R23(VDD_CORE3_2) U1.R25(VDD_CORE3_3) U1.T12(VDD_CORE1_152) U1.T14(VDD_CORE1_153) U1.T16(VDD_CORE1_154) U1.T18(VDD_CORE1_155) U1.T20(VDD_CORE1_156) U1.T22(VDD_CORE3_4) U1.T24(VDD_CORE3_5) U1.T26(VDD_CORE1_157) U1.U11(VDD_CORE1_158) U1.U13(VDD_CORE1_159) U1.U15(VDD_CORE1_160) U1.U17(VDD_CORE1_161) U1.U19(VDD_CORE1_162) U1.U21(VDD_CORE1_163) U1.U23(VDD_CORE3_6) U1.U25(VDD_CORE3_7) U1.V12(VDD_CORE1_164) U1.V14(VDD_CORE1_165) U1.V16(VDD_CORE1_166) U1.V18(VDD_CORE1_167) U1.V20(VDD_CORE1_168) U1.V22(VDD_CORE3_8) U1.V24(VDD_CORE3_9) U1.W11(VDD_CORE1_169) U1.W13(VDD_CORE1_170) U1.W15(VDD_CORE1_171) U1.W17(VDD_CORE1_172) U1.W19(VDD_CORE1_173) U1.W21(VDD_CORE1_174) U1.W23(VDD_CORE3_10) U1.W25(VDD_CORE3_11) U1.Y12(VDD_CORE1_175) U1.Y14(VDD_CORE1_176) U1.Y16(VDD_CORE1_177) U1.Y18(VDD_CORE1_178) U1.Y20(VDD_CORE1_179) U1.Y22(VDD_CORE3_12)
VDD_CORE_EN: R88.2(N2) TP58.1 U2.G13(PR5C/PCLKT1_0) U10.6(EN)
VDD_CORE_PGOOD: R87.1(N1) TP59.1 U1.N28(PWRGOOD1) U1.P28(PWRGOOD3) U2.E2(PL3B) U10.40(PWRGD)
VDDA_DDR0_32A: C44.1(N1) C116.1(N1) C186.1(N1) C187.1(N1) L7.2(N2) R144.2(N2) U1.AB10(VDDA_DDR0_32A) U1.AC10(VDDA_DDR0_32A_1)
VDDA_DDR0_32B: R145.2(N2) U1.AA10(VDDA_DDR0_32B) U1.Y10(VDDA_DDR0_32B_1)
VDDA_PCIE0: C37.1(N1) C89.1(N1) C90.1(N1) C169.1(N1) C170.1(N1) C278.1(N1) C279.1(N1) L2.2(N2) U1.AF12(VDDA_PCIE0) U1.AF13(VDDA_PCIE0_1) U1.AF14(VDDA_PCIE0_2)
VDDA_PLL: C25.1(N1) C26.1(N1) C27.1(N1) C28.1(N1) C29.1(N1) C57.1(N1) L13.2(N2) U1.AC18(VDDA_PLL5) U1.K27(VDDA_PLL3) U1.M27(VDDA_PLL1) U1.N27(VDDA_PLL0) U1.U10(VDDA_PLL2)
VDDA_SERDES: C40.1(N1) C92.1(N1) C93.1(N1) C94.1(N1) C171.1(N1) C172.1(N1) C280.1(N1) C281.1(N1) L3.2(N2) U1.AE22(VDDA_SERDES012) U1.AE23(VDDA_SERDES012_1) U1.AE24(VDDA_SERDES012_2) U1.AF22(VDDA_SERDES012_3) U1.AF23(VDDA_SERDES012_4)
VDDA_TS0: C74.1(N1) C86.1(N1) L14.1(N1) U1.M32(VDDA_TS0)
VDDAH_PCIE0: C30.1(N1) C38.1(N1) C39.1(N1) C91.1(N1) L1.2(N2) U1.AF16(VSS_60)
VDDAH_SERDES: C41.1(N1) C42.1(N1) C43.1(N1) C101.1(N1) C102.1(N1) C103.1(N1) L15.2(N2) U1.AF20(VSS_63) U1.AF21(SERDES0_APROBE)
VDDQ_VTT_EN: R105.2(N2) TP65.1 U2.H12(PR5D/PCLKC1_0) U3.16(S5) U3.17(S3)
VDDQ_VTT_PGOOD: R106.1(N1) TP60.1 U2.E1(PL3A) U3.20(PGOOD)
3N2284: R268.2(N2) U14.1(OE1)
3N2285: R269.2(N2) U14.11(OE2)
3N2286: R15.2(N2) U14.20(FSB1)
3N2287: R14.2(N2) U14.10(FSB2)
3N2290: R132.1(N1) U14.7(CLK1-)
3N2291: R133.1(N1) U14.8(CLK1+)
3N2301: R135.1(N1) U14.5(CLK0-)
3N2302: R134.1(N1) U14.6(CLK0+)
3N2521: R21.2(N2) U7.7(DQ3/HOLD_L) U15.7(DQ3/HOLD_L)
6N3961: R124.2(N2) R272.1(N1) U1.P7(DDR0_32A_DRAMRST_L)
6N3963: R310.1(N1) U1.P9(DDR0_32A_PAR_ERR_L)
6N4748: C105.1(N1) R7.2(N2) R8.2(N2)
9N1879: R264.1(N1) U2.A4(PT7A/TDO)
9N2032: R59.1(N1) U12.15(~OE)
9N2141: DS1.2(C2) R277.2(N2)
9N2152: DS1.3(C1) R276.2(N2)
10N2223: C46.1(N1) R117.1(N1)
10N2224: C47.1(N1) R116.1(N1)
10N2225: U5.3(NC1)
10N2227: U6.3(NC1)
10N2228: C32.2(N2) R119.1(N1)
10N2229: C32.1(N1) U6.4(BOOT)
10N2230: R170.2(N2) U6.39(DISB_L)
10N2232: C33.1(N1) U5.4(BOOT)
10N2233: C33.2(N2) R118.1(N1)
10N2235: R169.2(N2) U5.39(DISB_L)
10N2253: R126.2(N2) U6.1(ZCD_EN_L)
10N2256: R74.2(N2) U5.1(ZCD_EN_L)
10N2259: R118.2(N2) U5.7(PHASE)
10N2262: R119.2(N2) U6.7(PHASE)
10N2370: C124.1(N1) C143.1(N1) R401.2(N2) R402.2(N2) U10.30(VCC)
10N2381: R327.1(N1) U10.19(ILIMITFS)
10N2383: C81.1(N1) R120.1(N1) R326.2(N2)
10N2384: C48.1(N1) C52.1(N1) U10.14(COMP)
10N2385: C49.2(N2) R182.1(N1)
10N2386: C48.2(N2) R328.1(N1)
10N2397: R3.2(N2) U10.11(RAMPADJ)
10N2399: R308.2(N2) U10.10(RT)
10N2403: R181.1(N1) U10.26(PWM4)
10N2407: C144.1(N1) R3.1(N1) R312.2(N2)
10N2409: R180.1(N1) U10.27(PWM3)
10N2410: R110.1(N1) R111.1(N1) R287.2(N2)
10N2411: R1.2(N2) U10.9(IREF)
10N2412: C142.1(N1) U10.1(VCC3V3)
10N2498: R326.1(N1) U10.12(TRDET)
10N2504: C49.1(N1) C52.2(N2) R120.2(N2) R313.1(N1) R328.2(N2) U10.15(FB)
10N2528: C34.1(N1) C35.1(N1) R13.2(N2) R324.1(N1) R325.1(N1) U10.17(CSSUM)
10N2535: C50.1(N1) R287.1(N1) U10.16(CSREF)
11N1937: L19.2(N2) U9.5(SW3)
11N1952: C127.2(N2) L21.1(N1) U13.1(SW_1) U13.12(SW_4) U13.13(SW_3) U13.16(SW_2)
11N1953: R112.1(N1) R113.2(N2) U13.5(FB)
11N1966: R104.1(N1) U9.16(POR)
11N1968: L11.2(N2) U9.1(SW2)
11N1970: L10.2(N2) U9.27(SW1)
11N1971: L12.1(N1) U9.9(SW4)
11N1979: R98.1(N1) U9.12(STBY)
11N1981: C127.1(N1) U13.10(BST)
11N2138: R318.2(N2) U3.19(MODE)
11N2140: R107.2(N2) U3.18(TRIP)
11N2146: C31.1(N1) R4.2(N2) R127.1(N1) U3.8(REFIN)
11N2152: C128.1(N1) R127.2(N2) U3.6(VREF)
11N2159: C205.1(N1) R331.2(N2) U3.12(V5IN)
11N2173: Q1.3(TG) U3.14(DRVH)
11N2175: C129.2(N2) Q1.4(TGR) U3.13(SW)
11N2177: Q1.5(BG) U3.11(DRVL)
11N2179: R108.1(N1) U3.15(VBST)
11N2181: C129.1(N1) R108.2(N2)
11N2191: R335.1(N1) U3.9(VDDQSNS)
11N2199: R337.1(N1) U3.1(VTTSNS)
11N2202: C165.1(N1) U3.5(VTTREF)
11N2253: L9.1(N1) Q1.6(VSW1) Q1.7(VSW2) Q1.8(VSW3) R109.2(N2)
11N2258: C51.1(N1) R109.1(N1)
11N2296: L20.1(N1) U9.19(SW5)
12N2312: R189.2(N2) U17.L8(ZQ0)
12N3057: R352.2(N2) U18.L8(ZQ0)
12N3220: R353.2(N2) U19.L8(ZQ0)
12N3291: R340.1(N1) U19.D3(UDM)
12N3293: R338.1(N1) U19.B7(UDQS_L)
12N3294: R339.2(N2) U19.C7(UDQS)
13N4315: R371.1(N1) U20.15(~OE)
13N4321: C282.1(N1) R372.1(N1) R393.1(N1) U20.1(S)
13N4347: R375.1(N1) U21.15(~OE)
13N4351: C283.1(N1) R376.1(N1) R394.1(N1) U21.1(S)
_NC_156M_N: U14.15(CLK2-)
_NC_156M_P: U14.16(CLK2+)
_NC_B_AZQ: U1.L10(DDR0_32B_AZQ)
_NC_B_DZQ0: U1.H8(DDR0_32B_DZQ0)
_NC_B_DZQ1: U1.J10(DDR0_32B_DZQ1)
_NC_CLK_NC1: U14.2(NC1)
_NC_CLK_NC2: U14.12(NC2)
_NC_CLK_NC3: U14.17(NC3)
_NC_CLK_NC4: U14.18(NC4)
_NC_CPLD_0: U2.B1(NC_0)
_NC_CPLD_1: U2.B2(NC_1)
_NC_CPLD_2: U2.F1(NC_2)
_NC_CPLD_3: U2.F3(NC_3)
_NC_CPLD_4: U2.G1(NC_4)
_NC_CPLD_5: U2.N1(NC_5)
_NC_CPLD_6: U2.L3(NC_6)
_NC_CPLD_7: U2.P2(NC_7)
_NC_CPLD_8: U2.N2(NC_8)
_NC_CPLD_9: U2.N5(NC_9)
_NC_CPLD_10: U2.M5(NC_10)
_NC_CPLD_11: U2.M6(NC_11)
_NC_CPLD_12: U2.P9(NC_12)
_NC_CPLD_13: U2.N9(NC_13)
_NC_CPLD_14: U2.M11(NC_14)
_NC_CPLD_15: U2.P12(NC_15)
_NC_CPLD_16: U2.M14(NC_16)
_NC_CPLD_17: U2.M12(NC_17)
_NC_CPLD_18: U2.J14(NC_18)
_NC_CPLD_19: U2.J12(NC_19)
_NC_CPLD_20: U2.H14(NC_20)
_NC_CPLD_21: U2.A14(NC_21)
_NC_CPLD_22: U2.D12(NC_22)
_NC_CPLD_23: U2.C14(NC_23)
_NC_CPLD_24: U2.A12(NC_24)
_NC_CPLD_25: U2.C12(NC_25)
_NC_CPLD_26: U2.C11(NC_26)
_NC_CPLD_27: U2.A10(NC_27)
_NC_CPLD_28: U2.A8(NC_28)
_NC_CPLD_29: U2.C6(NC_29)
_NC_CPLD_30: U2.B5(NC_30)
_NC_CPLD_31: U2.C7(NC_31)
_NC_CPLD_GPIO8: U2.B12(PT11B)
_NC_DDR0_32A_A15: U1.W7(DDR0_32A_A15)
_NC_DDR0_32A_CK1_N: U1.U8(DDR0_32A_CK_L1)
_NC_DDR0_32A_CK1_P: U1.U7(DDR0_32A_CK_H1)
_NC_DDR0_32A_CKE1: U1.W8(DDR0_32A_CKE1)
_NC_DDR0_32A_CS1_L: U1.V9(DDR0_32A_CS_L1)
_NC_DDR0_32A_ODT1: U1.Y9(DDR0_32A_ODT1)
_NC_DDR0_32A_PAR_OUT: U1.N9(DDR0_32A_PAR_OUT)
_NC_DDR0_32B_A0: U1.G9(DDR0_32B_A0)
_NC_DDR0_32B_A1: U1.K7(DDR0_32B_A1)
_NC_DDR0_32B_A2: U1.G8(DDR0_32B_A2)
_NC_DDR0_32B_A3: U1.M6(DDR0_32B_A3)
_NC_DDR0_32B_A4: U1.J7(DDR0_32B_A4)
_NC_DDR0_32B_A5: U1.M7(DDR0_32B_A5)
_NC_DDR0_32B_A6: U1.K8(DDR0_32B_A6)
_NC_DDR0_32B_A7: U1.N7(DDR0_32B_A7)
_NC_DDR0_32B_A8: U1.L8(DDR0_32B_A8)
_NC_DDR0_32B_A9: U1.E6(DDR0_32B_A9)
_NC_DDR0_32B_A10: U1.D7(DDR0_32B_A10)
_NC_DDR0_32B_A11: U1.L7(DDR0_32B_A11)
_NC_DDR0_32B_A12: U1.G6(DDR0_32B_A12)
_NC_DDR0_32B_A13: U1.D8(DDR0_32B_A13)
_NC_DDR0_32B_A14: U1.N6(DDR0_32B_A14)
_NC_DDR0_32B_A15: U1.D6(DDR0_32B_A15)
_NC_DDR0_32B_BA0: U1.M8(DDR0_32B_BA0)
_NC_DDR0_32B_BA1: U1.C8(DDR0_32B_BA1)
_NC_DDR0_32B_BA2: U1.H7(DDR0_32B_BA2)
_NC_DDR0_32B_CAS_L: U1.K9(DDR0_32B_CAS_L)
_NC_DDR0_32B_CB0: U1.C5(DDR0_32B_CB0)
_NC_DDR0_32B_CB1: U1.D4(DDR0_32B_CB1)
_NC_DDR0_32B_CB2: U1.E2(DDR0_32B_CB2)
_NC_DDR0_32B_CB3: U1.D2(DDR0_32B_CB3)
_NC_DDR0_32B_CB4: U1.D1(DDR0_32B_CB4)
_NC_DDR0_32B_CB5: U1.D3(DDR0_32B_CB5)
_NC_DDR0_32B_CB6: U1.D5(DDR0_32B_CB6)
_NC_DDR0_32B_CB7: U1.C4(DDR0_32B_CB7)
_NC_DDR0_32B_CK0_N: U1.E9(DDR0_32B_CK_L0)
_NC_DDR0_32B_CK0_P: U1.F9(DDR0_32B_CK_H0)
_NC_DDR0_32B_CK1_N: U1.G7(DDR0_32B_CK_L1)
_NC_DDR0_32B_CK1_P: U1.H6(DDR0_32B_CK_H1)
_NC_DDR0_32B_CKE0: U1.E7(DDR0_32B_CKE0)
_NC_DDR0_32B_CKE1: U1.H9(DDR0_32B_CKE1)
_NC_DDR0_32B_CS0_L: U1.M9(DDR0_32B_CS_L0)
_NC_DDR0_32B_CS1_L: U1.J9(DDR0_32B_CS_L1)
_NC_DDR0_32B_DM0: U1.P1(DDR0_32B_DM0)
_NC_DDR0_32B_DM1: U1.L1(DDR0_32B_DM1)
_NC_DDR0_32B_DM2: U1.H2(DDR0_32B_DM2)
_NC_DDR0_32B_DM3: U1.E3(DDR0_32B_DM3)
_NC_DDR0_32B_DM4: U1.E1(DDR0_32B_DM4)
_NC_DDR0_32B_DQ0: U1.R4(DDR0_32B_DQ0)
_NC_DDR0_32B_DQ1: U1.R3(DDR0_32B_DQ1)
_NC_DDR0_32B_DQ2: U1.R1(DDR0_32B_DQ2)
_NC_DDR0_32B_DQ3: U1.M5(DDR0_32B_DQ3)
_NC_DDR0_32B_DQ4: U1.P4(DDR0_32B_DQ4)
_NC_DDR0_32B_DQ5: U1.R2(DDR0_32B_DQ5)
_NC_DDR0_32B_DQ6: U1.N4(DDR0_32B_DQ6)
_NC_DDR0_32B_DQ7: U1.N1(DDR0_32B_DQ7)
_NC_DDR0_32B_DQ8: U1.K5(DDR0_32B_DQ8)
_NC_DDR0_32B_DQ9: U1.M3(DDR0_32B_DQ9)
_NC_DDR0_32B_DQ10: U1.L4(DDR0_32B_DQ10)
_NC_DDR0_32B_DQ11: U1.M1(DDR0_32B_DQ11)
_NC_DDR0_32B_DQ12: U1.M2(DDR0_32B_DQ12)
_NC_DDR0_32B_DQ13: U1.L5(DDR0_32B_DQ13)
_NC_DDR0_32B_DQ14: U1.K4(DDR0_32B_DQ14)
_NC_DDR0_32B_DQ15: U1.M4(DDR0_32B_DQ15)
_NC_DDR0_32B_DQ16: U1.H5(DDR0_32B_DQ16)
_NC_DDR0_32B_DQ17: U1.H1(DDR0_32B_DQ17)
_NC_DDR0_32B_DQ18: U1.J5(DDR0_32B_DQ18)
_NC_DDR0_32B_DQ19: U1.H4(DDR0_32B_DQ19)
_NC_DDR0_32B_DQ20: U1.K2(DDR0_32B_DQ20)
_NC_DDR0_32B_DQ21: U1.K1(DDR0_32B_DQ21)
_NC_DDR0_32B_DQ22: U1.J4(DDR0_32B_DQ22)
_NC_DDR0_32B_DQ23: U1.H3(DDR0_32B_DQ23)
_NC_DDR0_32B_DQ24: U1.F5(DDR0_32B_DQ24)
_NC_DDR0_32B_DQ25: U1.G1(DDR0_32B_DQ25)
_NC_DDR0_32B_DQ26: U1.G4(DDR0_32B_DQ26)
_NC_DDR0_32B_DQ27: U1.F1(DDR0_32B_DQ27)
_NC_DDR0_32B_DQ28: U1.F2(DDR0_32B_DQ28)
_NC_DDR0_32B_DQ29: U1.F3(DDR0_32B_DQ29)
_NC_DDR0_32B_DQ30: U1.E5(DDR0_32B_DQ30)
_NC_DDR0_32B_DQ31: U1.G5(DDR0_32B_DQ31)
_NC_DDR0_32B_DQS0_N: U1.P3(DDR0_32B_DQS_L0)
_NC_DDR0_32B_DQS0_P: U1.N3(DDR0_32B_DQS_H0)
_NC_DDR0_32B_DQS1_N: U1.L3(DDR0_32B_DQS_L1)
_NC_DDR0_32B_DQS1_P: U1.L2(DDR0_32B_DQS_H1)
_NC_DDR0_32B_DQS2_N: U1.J2(DDR0_32B_DQS_L2)
_NC_DDR0_32B_DQS2_P: U1.J1(DDR0_32B_DQS_H2)
_NC_DDR0_32B_DQS3_N: U1.G2(DDR0_32B_DQS_L3)
_NC_DDR0_32B_DQS3_P: U1.G3(DDR0_32B_DQS_H3)
_NC_DDR0_32B_DQS4_N: U1.C3(DDR0_32B_DQS_L4)
_NC_DDR0_32B_DQS4_P: U1.C2(DDR0_32B_DQS_H4)
_NC_DDR0_32B_DRAMRST_L: U1.P6(DDR0_32B_DRAMRST_L)
_NC_DDR0_32B_ODT0: U1.L9(DDR0_32B_ODT0)
_NC_DDR0_32B_ODT1: U1.D9(DDR0_32B_ODT1)
_NC_DDR0_32B_PAR_ERR_L: U1.F7(DDR0_32B_PAR_ERR_L)
_NC_DDR0_32B_PAR_OUT: U1.F6(DDR0_32B_PAR_OUT)
_NC_DDR0_32B_RAS_L: U1.J8(DDR0_32B_RAS_L)
_NC_DDR0_32B_WE_L: U1.L6(DDR0_32B_WE_L)
_NC_ECC_DQ8: U19.D7(DQ8)
_NC_ECC_DQ9: U19.C3(DQ9)
_NC_ECC_DQ10: U19.C8(DQ10)
_NC_ECC_DQ11: U19.C2(DQ11)
_NC_ECC_DQ12: U19.A7(DQ12)
_NC_ECC_DQ13: U19.A2(DQ13)
_NC_ECC_DQ14: U19.B8(DQ14)
_NC_ECC_DQ15: U19.A3(DQ15)
_NC_FAN_PWM: U2.M7(PB10C/PCLKT2_1)
_NC_FAN_TACH: U2.N7(PB10B)
_NC_MIC7401_NC1: U9.33(NC1)
_NC_MIC7401_NC2: U9.34(NC2)
_NC_MIC24085_NC1: U13.6(NC_1)
_NC_MIC24085_NC2: U13.7(NC_2)
_NC_NCP4200_SW3: U10.23(SW3)
_NC_NCP4200_SW4: U10.22(SW4)
_NC_NCSI_CLK_IN: J4.70(ROW9)
_NC_NCSI_CRS_DV: J4.77(ROW10)
_NC_NCSI_RX_ER: J4.85(ROW11)
_NC_NCSI_RXD_0: J4.45(ROW6)
_NC_NCSI_RXD_1: J4.53(ROW7)
_NC_NCSI_TX_EN: J4.62(ROW8)
_NC_NCSI_TXD_0: J4.30(ROW4)
_NC_NCSI_TXD_1: J4.38(ROW5)
_NC_NFP_DDR0_32A_PLL_ATO: U1.AC9(DDR0_32A_PLL_ATO)
_NC_NFP_DDR0_32A_PLL_DTO0: U1.P10(DDR0_32A_PLL_DTO0)
_NC_NFP_DDR0_32A_PLL_DTO1: U1.R10(DDR0_32A_PLL_DTO1)
_NC_NFP_DDR0_32B_PLL_ATO: U1.M10(DDR0_32B_PLL_ATO)
_NC_NFP_DDR0_32B_PLL_DTO0: U1.C6(DDR0_32B_PLL_DTO0)
_NC_NFP_DDR0_32B_PLL_DTO1: U1.C7(DDR0_32B_PLL_DTO1)
_NC_NFP_GPIO6: U1.AA30(GPIO6)
_NC_NFP_GPIO19: U1.AE30(GPIO19)
_NC_NFP_GPIO20: U1.AF30(GPIO20)
_NC_NFP_GPIO21: U1.AE31(GPIO21)
_NC_NFP_GPIO22: U1.AF31(GPIO22)
_NC_NFP_GPIO23: U1.AE32(GPIO23)
_NC_NFP_PCIE0_APROBE1: U1.AF15(PCIE0_APROBE1)
_NC_NFP_PCIE0_APROBE2: U1.AF17(PCIE0_APROBE2)
_NC_NFP_PCIE1_APROBE1: U1.AF5(PCIE1_APROBE2)
_NC_NFP_PCIE1_APROBE2: U1.AF7(PCIE1_APROBE1)
_NC_NFP_PCIE1_PET0_N: U1.AK4(PCIE1_TXN0)
_NC_NFP_PCIE1_PET0_P: U1.AL4(PCIE1_TXP0)
_NC_NFP_PCIE1_PET1_N: U1.AL5(PCIE1_TXN1)
_NC_NFP_PCIE1_PET1_P: U1.AM5(PCIE1_TXP1)
_NC_NFP_PCIE1_PET2_N: U1.AK6(PCIE1_TXN2)
_NC_NFP_PCIE1_PET2_P: U1.AL6(PCIE1_TXP2)
_NC_NFP_PCIE1_PET3_N: U1.AL7(PCIE1_TXN3)
_NC_NFP_PCIE1_PET3_P: U1.AM7(PCIE1_TXP3)
_NC_NFP_PCIE1_PET4_N: U1.AK8(PCIE1_TXN4)
_NC_NFP_PCIE1_PET4_P: U1.AL8(PCIE1_TXP4)
_NC_NFP_PCIE1_PET5_N: U1.AL9(PCIE1_TXN5)
_NC_NFP_PCIE1_PET5_P: U1.AM9(PCIE1_TXP5)
_NC_NFP_PCIE1_PET6_N: U1.AK10(PCIE1_TXN6)
_NC_NFP_PCIE1_PET6_P: U1.AL10(PCIE1_TXP6)
_NC_NFP_PCIE1_PET7_N: U1.AL11(PCIE1_TXN7)
_NC_NFP_PCIE1_PET7_P: U1.AM11(PCIE1_TXP7)
_NC_NFP_SERDES0_APROBE: U1.AF19(VSS_62)
_NC_NFP_SERDES0_TX1_N: U1.AL21(SERDES0_TXN1)
_NC_NFP_SERDES0_TX1_P: U1.AM21(SERDES0_TXP1)
_NC_NFP_SERDES0_TX2_N: U1.AK22(SERDES0_TXN2)
_NC_NFP_SERDES0_TX2_P: U1.AL22(SERDES0_TXP2)
_NC_NFP_SERDES0_TX3_N: U1.AL23(SERDES0_TXN3)
_NC_NFP_SERDES0_TX3_P: U1.AM23(SERDES0_TXP3)
_NC_NFP_SERDES1_APROBE: U1.AF25(SERDES1_APROBE)
_NC_NFP_SERDES2_APROBE: U1.AF27(SERDES2_APROBE)
_NC_NFP_SERDES2_TX0_N: U1.AK28(SERDES2_TXN0)
_NC_NFP_SERDES2_TX0_P: U1.AL28(SERDES2_TXP0)
_NC_NFP_SERDES2_TX1_N: U1.AL29(SERDES2_TXN1)
_NC_NFP_SERDES2_TX1_P: U1.AM29(SERDES2_TXP1)
_NC_NFP_SPI3_MOSI: U1.T30(SPI3_MOSI)
_NC_NFP_SPIX_SEL1: U1.W32(SPIX_SEL1)
_NC_NFP_SPIX_SEL3: U1.R32(SPIX_SEL3)
_NC_NFP_TD_TDA: U1.K30(TD_TDA)
_NC_NFP_TD_TDC: U1.K29(TD_TDC)
_NC_NFP_TEST_EDM: U1.AK31(TEST_EDM)
_NC_NFP_TS_DFTANATP_AQ0: U1.K28(TS_DFTANATP_AQ0)
_NC_NFP_TS_DFTANATP_AQ1: U1.L28(TS_DFTANATP_AQ1)
_NC_NFP_TS_TDA: U1.L32(TS_TDA)
_NC_NFP_TS_TDC: U1.K32(TS_TDC)
_NC_NWK0_LED_ACT_Y_L: U2.A3(PT6C)
_NC_NWK0_LED_LINK_Y_L: U2.A2(PT6A)
_NC_NWK0_MOD_INT_L: U2.A7(PT9A/PCLKT0_1)
_NC_NWK0_MOD_LP_MODE: U2.C9(PT10A)
_NC_NWK0_MOD_RESET_L: U2.A9(PT10B)
_NC_NWK0_MOD_RS_1: U2.C10(PT10D/PROGRAMN)
_NC_NWK0_MOD_SEL_L: U2.B9(PT10C/JTAGENB)
_NC_NWK1_LED_ACT_Y_L: U2.B13(PT11C/INITN)
_NC_NWK1_LED_LINK_Y_L: U2.A11(PT11A)
_NC_NWK1_MOD_INT_L: U2.B14(PR2A)
_NC_NWK1_MOD_LP_MODE: U2.E12(PR2C)
_NC_NWK1_MOD_RESET_L: U2.E14(PR2D)
_NC_NWK1_MOD_RS_1: U2.F12(PR3B)
_NC_NWK1_MOD_SEL_L: U2.E13(PR3A)
_NC_SPI3_SCK: U1.U28(SPI3_SCK)
_NC_SPIX_D3: U1.R30(SPIX_D3)
_NC_SPIX_HOLD_L: U1.V32(SPIX_HOLD_L)
_NC_TEST_SCAN_0_OUT0: U1.J32(TEST_SCAN_0_OUT0)
_NC_TEST_SCAN_0_OUT1: U1.J31(TEST_SCAN_0_OUT1)
_NC_TEST_SCAN_0_OUT2: U1.J30(TEST_SCAN_0_OUT2)
_NC_TEST_SCAN_0_OUT3: U1.J29(TEST_SCAN_0_OUT3)
_NC_TEST_SCAN_0_OUT4: U1.J28(TEST_SCAN_0_OUT4)
_NC_TEST_SCAN_0_OUT5: U1.H31(TEST_SCAN_0_OUT5)
_NC_TEST_SCAN_0_OUT6: U1.H29(TEST_SCAN_0_OUT6)
_NC_TEST_SCAN_0_OUT7: U1.H28(TEST_SCAN_0_OUT7)
_NC_TEST_SCAN_0_OUT8: U1.H30(TEST_SCAN_0_OUT8)
_NC_TEST_SCAN_0_OUT9: U1.H32(TEST_SCAN_0_OUT9)
_NC_TEST_SCAN_0_OUT10: U1.G32(TEST_SCAN_0_OUT10)
_NC_TEST_SCAN_0_OUT11: U1.G29(TEST_SCAN_0_OUT11)
_NC_TEST_SCAN_0_OUT12: U1.G28(TEST_SCAN_0_OUT12)
_NC_TEST_SCAN_0_OUT13: U1.F32(TEST_SCAN_0_OUT13)
_NC_TEST_SCAN_0_OUT14: U1.F30(TEST_SCAN_0_OUT14)
_NC_TEST_SCAN_0_OUT15: U1.F29(TEST_SCAN_0_OUT15)
_NC_TEST_SCAN_0_OUT16: U1.F28(TEST_SCAN_0_OUT16)
_NC_TEST_SCAN_0_OUT17: U1.G30(TEST_SCAN_0_OUT17)
_NC_TEST_SCAN_0_OUT18: U1.E32(TEST_SCAN_0_OUT18)
_NC_TEST_SCAN_0_OUT19: U1.E31(TEST_SCAN_0_OUT19)
_NC_TEST_SCAN_0_OUT20: U1.E30(TEST_SCAN_0_OUT20)
_NC_TEST_SCAN_0_OUT21: U1.E29(TEST_SCAN_0_OUT21)
_NC_TEST_SCAN_0_OUT22: U1.D31(TEST_SCAN_0_OUT22)
_NC_TEST_SCAN_0_OUT23: U1.D30(TEST_SCAN_0_OUT23)
_NC_TEST_SCAN_0_OUT24: U1.C31(TEST_SCAN_0_OUT24)
_NC_TEST_SCAN_0_OUT25: U1.C30(TEST_SCAN_0_OUT25)
_NC_TEST_SCAN_0_OUT26: U1.D32(TEST_SCAN_0_OUT26)
_NC_TEST_SCAN_0_OUT27: U1.A28(TEST_SCAN_0_OUT27)
_NC_TEST_SCAN_0_OUT28: U1.B29(TEST_SCAN_0_OUT28)
_NC_TEST_SCAN_0_OUT29: U1.C28(TEST_SCAN_0_OUT29)
_NC_TEST_SCAN_0_OUT30: U1.A29(TEST_SCAN_0_OUT30)
_NC_TEST_SCAN_0_OUT31: U1.C29(TEST_SCAN_0_OUT31)
_NC_TEST_SCAN_0_OUT32: U1.D29(TEST_SCAN_0_OUT32)
_NC_TEST_SCAN_0_OUT33: U1.A27(TEST_SCAN_0_OUT33)
_NC_TEST_SCAN_0_OUT34: U1.B28(TEST_SCAN_0_OUT34)
_NC_TEST_SCAN_0_OUT35: U1.B27(TEST_SCAN_0_OUT35)
_NC_TEST_SCAN_0_OUT36: U1.D27(TEST_SCAN_0_OUT36)
_NC_TEST_SCAN_0_OUT37: U1.C27(TEST_SCAN_0_OUT37)
_NC_U20_74CBTLV_1B1: U20.2(1B1)
_NC_U20_74CBTLV_2B1: U20.5(2B1)
_NC_U20_74CBTLV_3B1: U20.11(3B1)
_NC_U20_74CBTLV_4B1: U20.14(4B1)
_NC_U21_74CBTLV_1B1: U21.2(1B1)
_NC_U21_74CBTLV_2B1: U21.5(2B1)
_NC_U21_74CBTLV_3B1: U21.11(3B1)
_NC_U21_74CBTLV_4B1: U21.14(4B1)
_NC_VDD_CORE3_SENSE: U1.Y24(VDD_CORE3_SENSE)
_NC_VDDQ_TEST_SCAN_0_OUT: U1.B30(VDDQ_TEST_SCAN_0_OUT)
_NC_VDDQ_TEST_SCAN_0_OUT_1: U1.E28(VDDQ_TEST_SCAN_0_OUT_1)
_NC_VDDQ_TEST_SCAN_0_OUT_2: U1.G31(VDDQ_TEST_SCAN_0_OUT_2)
_NC_VDDQ_TEST_SCAN_0_OUT_3: U1.J27(VDDQ_TEST_SCAN_0_OUT_3)
_NC_VSS_SENSE: U1.Y23(VSS_SENSE3)
_NFP_ARM_SPI_FLASH_MOSI: R201.1(N1) U1.U31(SPI0_MOSI)
_NFP_ARM_SPI_FLASH_SCK: R204.1(N1) U1.R29(SPI0_SCK)
_NFP_ARM_SPI_FLASH_SEL: R282.1(N1) U1.U32(SPI0_SEL)
_NFP_CFG_SPI_FLASH_MOSI: R202.1(N1) U1.U30(SPI1_CFG_MOSI)
_NFP_CFG_SPI_FLASH_SCK: R205.1(N1) U1.T31(SPI1_CFG_SCK)
_NFP_CFG_SPI_FLASH_SEL: R281.1(N1) U1.T32(SPI1_CFG_SEL)
_NFP_CLK_NRESET_L: R47.1(N1) R410.1(N1) U2.M13(PR7B)
_NFP_CORE_VID0: R83.2(N2) R84.1(N1) R179.2(N2) U10.38(VID0)
_NFP_CORE_VID1: R92.1(N1) R97.2(N2) R176.2(N2) U10.37(VID1)
_NFP_CORE_VID2: R93.1(N1) R96.2(N2) R172.2(N2) U10.36(VID2)
_NFP_CORE_VID3: R94.1(N1) R95.2(N2) R175.2(N2) U10.35(VID3)
_NFP_CORE_VID4: R90.1(N1) R91.2(N2) R174.2(N2) U10.34(VID4)
_NFP_CORE_VID5: R77.1(N1) R82.2(N2) R177.2(N2) U10.33(VID5)
_NFP_CORE_VID6: R78.1(N1) R80.2(N2) R173.2(N2) U10.32(VID6)
_NFP_CORE_VID7: R79.1(N1) R81.2(N2) R178.2(N2) U10.31(VID7)
_NFP_JTAG_ARM_TDO: R263.1(N1) U1.Y30(JTAG_ARM_TDO)
_NFP_PCIE0_PER0_N: C154.1(N1) U1.AK12(PCIE0_TXN0)
_NFP_PCIE0_PER0_P: C153.1(N1) U1.AL12(PCIE0_TXP0)
_NFP_PCIE0_PER1_N: C156.1(N1) U1.AL13(PCIE0_TXN1)
_NFP_PCIE0_PER1_P: C155.1(N1) U1.AM13(PCIE0_TXP1)
_NFP_PCIE0_PER2_N: C158.1(N1) U1.AK14(PCIE0_TXN2)
_NFP_PCIE0_PER2_P: C157.1(N1) U1.AL14(PCIE0_TXP2)
_NFP_PCIE0_PER3_N: C160.1(N1) U1.AL15(PCIE0_TXN3)
_NFP_PCIE0_PER3_P: C159.1(N1) U1.AM15(PCIE0_TXP3)
_NFP_PCIE0_PER4_N: C146.1(N1) U1.AK16(PCIE0_TXN4)
_NFP_PCIE0_PER4_P: C145.1(N1) U1.AL16(PCIE0_TXP4)
_NFP_PCIE0_PER5_N: C148.1(N1) U1.AL17(PCIE0_TXN5)
_NFP_PCIE0_PER5_P: C147.1(N1) U1.AM17(PCIE0_TXP5)
_NFP_PCIE0_PER6_N: C150.1(N1) U1.AK18(PCIE0_TXN6)
_NFP_PCIE0_PER6_P: C149.1(N1) U1.AL18(PCIE0_TXP6)
_NFP_PCIE0_PER7_N: C152.1(N1) U1.AL19(PCIE0_TXN7)
_NFP_PCIE0_PER7_P: C151.1(N1) U1.AM19(PCIE0_TXP7)
_NFP_PCIE0_RESET_OUT_L: R365.1(N1) R409.1(N1) U1.N30(PCIE0_RESET_OUT_L)
_NFP_PCIE1_RESET_OUT_L: U1.P32(PCIE1_RESET_OUT_L)
_NFP_SPI2_MOSI: R203.1(N1) U1.U29(SPI2_MOSI)
_NFP_SPI2_SCK: R199.1(N1) U1.T29(SPI2_SCK)
_NFP_UART_SR_TX: R200.1(N1) U1.N32(SR_TX)
_PGRM_JTAG_TDO: R262.1(N1) U1.AC32(JTAG_TDO)
_PSU_I2C_SCL: R138.1(N1) U1.AB29(GPIO8)
_PSU_I2C_SDA: R139.1(N1) U1.AB28(GPIO9)
_SW1: R314.1(N1) U10.25(SW1)
_SW2: R315.1(N1) U10.24(SW2)
A_AZQ: R188.2(N2) U1.AA9(DDR0_32A_AZQ)
A_DZQ0: R187.2(N2) U1.N10(DDR0_32A_DZQ0)
A_DZQ1: R186.2(N2) U1.K10(DDR0_32A_DZQ1)
CNTRL_SPI_CS: J5.24 TP4.1 U2.K2(PL6D)
CNTRL_SPI_MISO: J5.22 TP3.1 U2.J3(PL6C)
CNTRL_SPI_MOSI: J5.20 TP2.1 U2.K1(PL7A/PCLKT3_0)
CNTRL_SPI_SCK: J5.18 TP57.1 U2.J2(PL6B)
CORE_FB_ALERT_L: R86.1(N1) U2.F2(PL3D) U10.2(~ALERT)
CORE_FB_FAULT_L: R85.1(N1) U2.E3(PL3C) U10.3(~FAULT)
CORE_FB_PH1_THERM_L: R75.1(N1) TP35.1 U2.G3(PL5A/PCLKT3_1) U6.38(THWN)
CORE_FB_PH2_THERM_L: R76.1(N1) TP34.1 U2.H2(PL5B/PCLKC3_1) U5.38(THWN)
CPLD_CORE_PSI_L: R89.1(N1) U2.G12(PR5A) U10.39(PSI_L)
CPLD_GPIO_0: J5.1 TP22.1 U2.P8(PB12A)
CPLD_GPIO_1: J5.2 TP21.1 U2.M8(PB12B)
CPLD_GPIO_2: J5.29 TP20.1 U2.P3(PB4A/CSSPIN)
CPLD_GPIO_3: J5.30 TP23.1 U2.M3(PB4B)
CPLD_NFP_RST_LED_L: R276.1(N1) U2.F13(PR3C)
CPLD_NIC_MEZZ_ID0: J4.5(ROW1) R396.2(N2) U2.N12(PB14C/SN)
CPLD_NIC_MEZZ_ID1: J4.139(ROW18) R395.2(N2) U2.H3(PL5D)
CPLD_PCIE0_WAKE_L: R367.1(N1) R397.2(N2) U2.P4(PB4D)
CPLD_PGRM_JTAG_SEL: R60.1(N1) U1.AB27(GPIO10) U12.1(S)
CPLD_PGRM_JTAG_TCK: R72.1(N1) U2.B6(PT7C/TCK) U12.4(1A)
CPLD_PGRM_JTAG_TDI: R63.2(N2) R159.1(N1) U2.B4(PT7B/TDI) U12.7(2A)
CPLD_PGRM_JTAG_TDO: R62.2(N2) R159.2(N2) R264.2(N2) U12.9(3A)
CPLD_PGRM_JTAG_TMS: R61.2(N2) U2.A6(PT7D/TMS) U12.12(4A)
CPLD_SMBUS_ALERT_L: R392.1(N1) U2.K13(PR6C)
CPLD_SMBUS_SCL: R390.1(N1) R399.2(N2) U2.P7(PB10A)
CPLD_SMBUS_SDA: R350.1(N1) R398.2(N2) U2.N6(PB6C/PCLKT2_0)
CPLD_VERSION_0: R49.1(N1) R50.2(N2) U2.N8(PB10D/PCLKC2_1)
CPLD_VERSION_1: R52.2(N2) R55.1(N1) U2.M9(PB12C)
CPLD_VERSION_2: R53.2(N2) R54.1(N1) U2.N10(PB12D)
DDR0_32A_A0: R206.1(N1) U1.AD8(DDR0_32A_A0) U17.N3(A0) U18.N3(A0) U19.N3(A0) V1_A-A00.1(PIN) V2_A-A00.1(PIN) V3_A-A00.1(PIN)
DDR0_32A_A1: R207.1(N1) U1.T7(DDR0_32A_A1) U17.P7(A1) U18.P7(A1) U19.P7(A1) V1_A-A01.1(PIN) V2_A-A01.1(PIN) V3_A-A01.1(PIN)
DDR0_32A_A2: R208.1(N1) U1.AD9(DDR0_32A_A2) U17.P3(A2) U18.P3(A2) U19.P3(A2) V1_A-A02.1(PIN) V2_A-A02.1(PIN) V3_A-A02.1(PIN)
DDR0_32A_A3: R209.1(N1) U1.T8(DDR0_32A_A3) U17.N2(A3) U18.N2(A3) U19.N2(A3) V1_A-A03.1(PIN) V2_A-A03.1(PIN) V3_A-A03.1(PIN)
DDR0_32A_A4: R210.1(N1) U1.AC8(DDR0_32A_A4) U17.P8(A4) U18.P8(A4) U19.P8(A4) V1_A-A04.1(PIN) V2_A-A04.1(PIN) V3_A-A04.1(PIN)
